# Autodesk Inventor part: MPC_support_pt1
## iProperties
Shininess: 64.0
Length Units: 11272
Angle Units: 11279
Time Units: 11290
Mass Units: 11286
Length Display Precision: 3
Angle Display Precision: 2
Compacted: True
Part Number: MPC_support_pt1
Document SubType Name: Modeling
Created: 2004-08
Designer: John Blackburn
Manufacturer: Standard
Standards Organization: Custom
Density: 0.0
Volumn: 0.0
Area: 0.0
PropertySet Name: Model Information
Control State: 0
Master: False
Checked Out: False
Author: John Blackburn
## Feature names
1. Base1
